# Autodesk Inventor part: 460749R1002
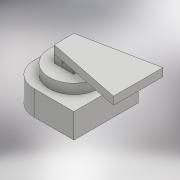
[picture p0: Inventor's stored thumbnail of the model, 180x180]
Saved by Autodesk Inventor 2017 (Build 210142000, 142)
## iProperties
Created: 2016-07
Part Number: 460749R1002
Material: Generic
Document SubType Name: Modeling
Designer: Polytech
Density: 1 g/cm^3
Appearance: Default
Author: Polytech
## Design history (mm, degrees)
sketch "Sketch1"
  geometry: C1 r 23 at (0, 0); 1 further point
  constraints: 1 centre point, 1 coincident
  dimensions: "d0" = 46 diameter of C1
extrude "Extrusion1" new body sketch "Sketch1" distance "d1" = 18; taper "d2" = 0 deg
sketch "Sketch2"
  geometry: L1 (-11.75, 48.75)-(48.75, 48.75); L2 (48.75, 48.75)-(48.75, -48.75); L3 (48.75, -48.75)-(-11.75, -48.75); L4 (-48.75, -11.75)-(-48.75, 11.75); L5 (-48.75, 48.75)-(48.75, -48.75); L6 (48.75, 48.75)-(-48.75, -48.75); A1 r 37 centre (-11.75, 11.75) between (-11.75, 48.75) and (-48.75, 11.75); A2 r 37 centre (-11.75, -11.75) between (-48.75, -11.75) and (-11.75, -48.75); 1 further point
  constraints: 12 end point, 4 point on circle, 4 point on line, 4 tangent, 2 centre point, 2 midpoint, 2 parallel, 1 equal radius, 1 horizontal, 1 perpendicular
  dimensions: "d3" = 97.5 distance of L2.end L6.end; "d4" = 97.5 distance of L1.end L2.end; "d5" = 37 radius of A1
extrude "Extrusion2" join sketch "Sketch2" distance "d6" = 37.5; taper "d7" = 0 deg
sketch "Sketch3"
  geometry: C1 r 37.5 at (0, 0); 1 further point
  constraints: 1 centre point, 1 coincident
  dimensions: "d8" = 75 diameter of C1
extrude "Extrusion3" join sketch "Sketch3" distance "d9" = 15; taper "d10" = 0 deg
sketch "Sketch4"
  geometry: L1 (-15, 15)-(15, 15); L2 (15, 15)-(15, -15); L3 (15, -15)-(-15, -15); L4 (-15, -15)-(-15, 15); L5 (-15, 15)-(15, -15); L6 (15, 15)-(-15, -15); 1 further point
  constraints: 12 end point, 2 midpoint, 2 parallel, 1 horizontal, 1 perpendicular
  dimensions: "d11" = 30 distance of L2.end L3.end; "d12" = 30 distance of L1.end L2.end
extrude "Extrusion4" join sketch "Sketch4" distance "d13" = 12; taper "d14" = 0 deg
sketch "Sketch5"
  geometry: L1 (-15, 6)-(15, 6); L2 (15, 6)-(15, -6); L3 (15, -6)-(-15, -6); L4 (-15, -6)-(-15, 6); L5 (-15, 6)-(15, -6); L6 (15, 6)-(-15, -6); 1 further point
  constraints: 12 end point, 2 midpoint, 2 parallel, 1 horizontal, 1 perpendicular
  dimensions: "d15" = 30 distance of L2.end L3.end; "d16" = 12 distance of L1.end L2.end
extrude "Extrusion5" cut sketch "Sketch5" distance "d17" = 12; taper "d18" = 0 deg
sketch "Sketch6"
  geometry: L1 (52.5, 0)-(-22.5, 0) reference; C1 r 3 at (15, 6); 1 further point
  constraints: 1 centre point, 1 vertical alignment
  dimensions: "d19" = 6 diameter of C1; "d20" = 6 distance from line of L1 C1.centre
extrude "Extrusion6" cut sketch "Sketch6" stored distance "d21" = 12; taper "d22" = 0 deg
sketch "Sketch7"
  geometry: 1 further point
sketch "Sketch8"
  geometry: L1 (-15, 15)-(-15, -15); L2 (-15, -15)-(97.5, -37.5); L3 (97.5, -37.5)-(97.5, 37.5); L4 (97.5, 37.5)-(-15, 15); 4 further points
  constraints: 8 end point, 2 coincident, 1 horizontal alignment, 1 midpoint, 1 parallel, 1 vertical
  dimensions: "d23" = 97.5 distance from line of L3 point (0, 0); "d24" = 75 distance of L2.end L3.end
extrude "Extrusion7" join sketch "Sketch8" distance "d25" = 12; taper "d26" = 0 deg
sketch "Sketch9"
  geometry: C1 r 23 at (0, 0); 1 further point
  constraints: 1 centre point, 1 coincident
  dimensions: "d27" = 46 diameter of C1
extrude "Extrusion8" cut sketch "Sketch9" distance "d28" = 24.5; taper "d29" = 0 deg
body "Solid1"
